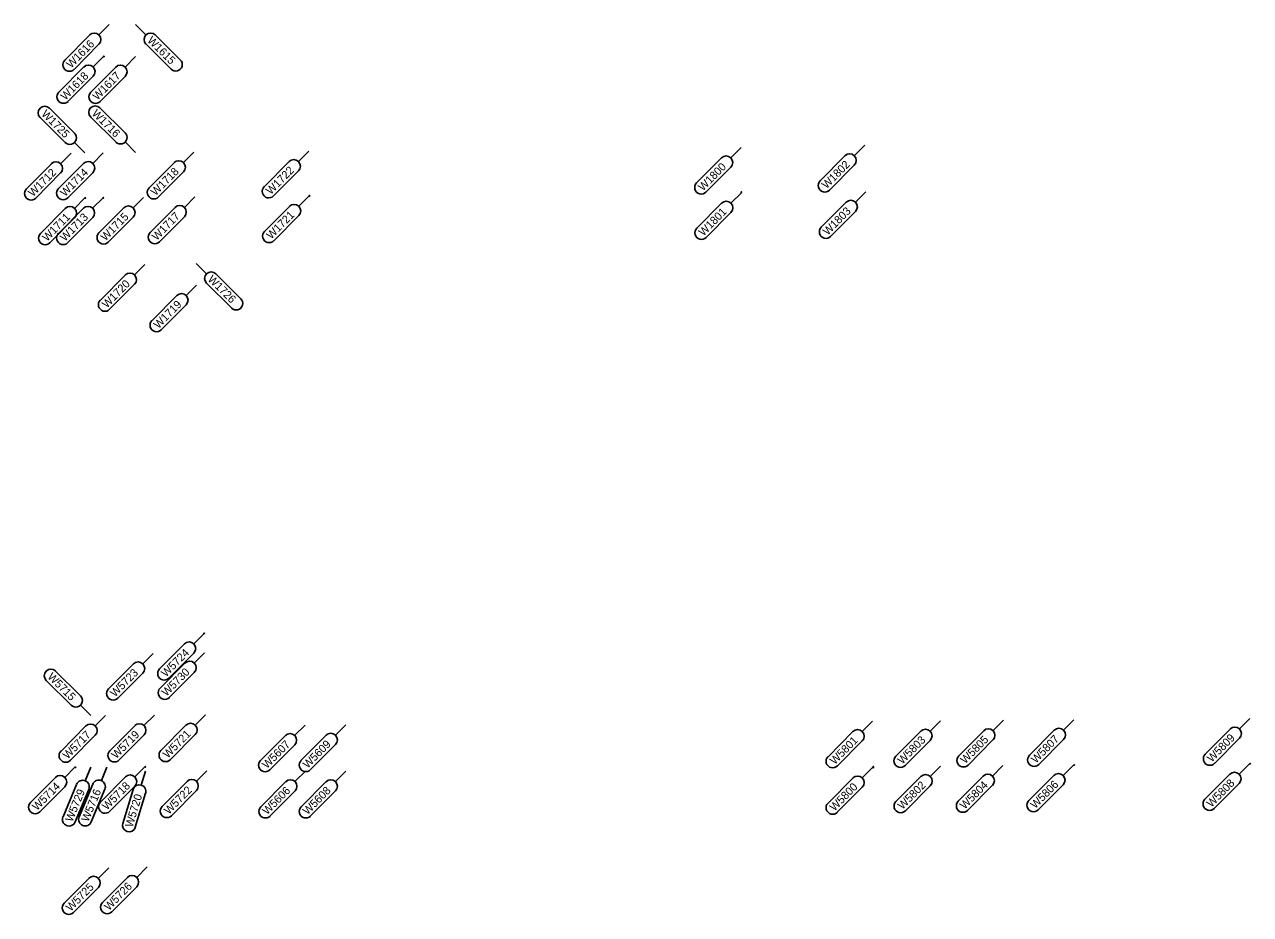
# Model space of a CAD drawing. Extents: x 12479652 to 12487250, y 9842710 to 9846560.
# Drawn here: x 12482796.2 to 12482987.8, y 9842724.8 to 9842863.8 of the extents above; entities that cross this region are included whole.
import ezdxf

# ---------------------------------------------------------------- set-up
doc = ezdxf.new("R2010")
doc.units = 0
doc.layers.add('_CIVIL_CONSTRUCTION', color=7, linetype='Continuous')
doc.layers.add('TextAlignmentLrg', color=7, linetype='Continuous')

msp = doc.modelspace()

# ---------------------------------------------------------------- linework, layer by layer
at = {"layer": '_CIVIL_CONSTRUCTION'}
for p, q in [((12482809.48, 9842863.78), (12482807.86, 9842862.15)), ((12482813.58, 9842863.77), (12482815.21, 9842862.15)), ((12482802.52, 9842858.23), (12482806.41, 9842862.14)), ((12482807.86, 9842860.7), (12482803.98, 9842856.78)), ((12482819.13, 9842856.81), (12482815.22, 9842860.7)), ((12482816.67, 9842862.15), (12482820.58, 9842858.26)), ((12482808.57, 9842858.78), (12482806.95, 9842857.15)), ((12482813.57, 9842858.77), (12482811.95, 9842857.14)), ((12482801.61, 9842853.23), (12482805.5, 9842857.15)), ((12482806.61, 9842853.22), (12482810.5, 9842857.13)), ((12482806.95, 9842855.7), (12482803.06, 9842851.79)), ((12482811.95, 9842855.69), (12482808.06, 9842851.77)), ((12482802.59, 9842845.36), (12482798.68, 9842849.25)), ((12482800.12, 9842850.71), (12482804.04, 9842846.82)), ((12482810.49, 9842845.44), (12482806.58, 9842849.33)), ((12482808.03, 9842850.78), (12482811.94, 9842846.89)), ((12482805.67, 9842843.75), (12482804.04, 9842845.37)), ((12482813.58, 9842843.82), (12482811.94, 9842845.44)), ((12482803.5, 9842843.68), (12482801.88, 9842842.05)), ((12482808.53, 9842843.72), (12482806.9, 9842842.09)), ((12482822.68, 9842843.85), (12482821.06, 9842842.22)), ((12482840.65, 9842844.01), (12482839.03, 9842842.38)), ((12482908.21, 9842844.59), (12482906.58, 9842842.96)), ((12482927.5, 9842844.92), (12482925.87, 9842843.29)), ((12482796.54, 9842838.13), (12482800.43, 9842842.04)), ((12482801.56, 9842838.17), (12482805.45, 9842842.09)), ((12482815.72, 9842838.3), (12482819.61, 9842842.21)), ((12482833.69, 9842838.46), (12482837.58, 9842842.38)), ((12482901.24, 9842839.04), (12482905.13, 9842842.95)), ((12482906.59, 9842841.51), (12482902.7, 9842837.6)), ((12482920.53, 9842839.38), (12482924.42, 9842843.29)), ((12482925.88, 9842841.84), (12482921.99, 9842837.93)), ((12482801.88, 9842840.6), (12482797.99, 9842836.68)), ((12482806.91, 9842840.64), (12482803.02, 9842836.73)), ((12482821.07, 9842840.77), (12482817.18, 9842836.85)), ((12482839.04, 9842840.93), (12482835.15, 9842837.02)), ((12482927.68, 9842837.67), (12482926.06, 9842836.04)), ((12482805.68, 9842836.7), (12482804.06, 9842835.07)), ((12482808.51, 9842836.72), (12482806.88, 9842835.09)), ((12482814.83, 9842836.78), (12482813.21, 9842835.15)), ((12482822.83, 9842836.86), (12482821.21, 9842835.23)), ((12482840.71, 9842837.03), (12482839.08, 9842835.4)), ((12482901.26, 9842831.97), (12482905.15, 9842835.89)), ((12482908.23, 9842837.52), (12482906.6, 9842835.89)), ((12482920.72, 9842832.12), (12482924.61, 9842836.03)), ((12482798.72, 9842831.15), (12482802.61, 9842835.06)), ((12482801.54, 9842831.17), (12482805.43, 9842835.09)), ((12482807.87, 9842831.23), (12482811.76, 9842835.14)), ((12482815.87, 9842831.31), (12482819.76, 9842835.22)), ((12482821.21, 9842833.77), (12482817.32, 9842829.86)), ((12482833.74, 9842831.48), (12482837.63, 9842835.39)), ((12482839.09, 9842833.95), (12482835.2, 9842830.03)), ((12482906.61, 9842834.44), (12482902.72, 9842830.53)), ((12482926.06, 9842834.59), (12482922.17, 9842830.67)), ((12482804.07, 9842833.62), (12482800.18, 9842829.7)), ((12482806.89, 9842833.64), (12482803, 9842829.73)), ((12482813.21, 9842833.7), (12482809.32, 9842829.78)), ((12482815.05, 9842826.31), (12482813.43, 9842824.68)), ((12482823.05, 9842826.48), (12482824.68, 9842824.86)), ((12482808.09, 9842820.76), (12482811.98, 9842824.67)), ((12482826.13, 9842824.86), (12482830.04, 9842820.97)), ((12482813.43, 9842823.23), (12482809.54, 9842819.32)), ((12482823.12, 9842823.1), (12482821.5, 9842821.47)), ((12482828.6, 9842819.52), (12482824.68, 9842823.41)), ((12482816.16, 9842817.55), (12482820.05, 9842821.46)), ((12482821.5, 9842820.01), (12482817.61, 9842816.1)), ((12482824.31, 9842768.71), (12482822.69, 9842767.08)), ((12482817.35, 9842763.16), (12482821.24, 9842767.07)), ((12482816.32, 9842765.58), (12482814.7, 9842763.95)), ((12482822.69, 9842765.62), (12482818.8, 9842761.71)), ((12482824.37, 9842765.7), (12482822.75, 9842764.07)), ((12482809.36, 9842760.03), (12482813.25, 9842763.94)), ((12482817.41, 9842760.15), (12482821.3, 9842764.06)), ((12482803.54, 9842757.49), (12482799.62, 9842761.38)), ((12482801.07, 9842762.83), (12482804.98, 9842758.94)), ((12482814.71, 9842762.5), (12482810.82, 9842758.59)), ((12482822.75, 9842762.62), (12482818.86, 9842758.7)), ((12482806.62, 9842755.87), (12482804.99, 9842757.49)), ((12482808.91, 9842755.89), (12482807.29, 9842754.26)), ((12482816.53, 9842755.94), (12482814.9, 9842754.31)), ((12482824.53, 9842756), (12482822.9, 9842754.36)), ((12482987.67, 9842755.42), (12482986.05, 9842753.79)), ((12482801.95, 9842750.34), (12482805.84, 9842754.25)), ((12482809.56, 9842750.39), (12482813.45, 9842754.3)), ((12482817.56, 9842750.45), (12482821.45, 9842754.36)), ((12482840.06, 9842754.39), (12482838.44, 9842752.76)), ((12482846.43, 9842754.44), (12482844.81, 9842752.8)), ((12482921.77, 9842749.46), (12482925.66, 9842753.37)), ((12482928.73, 9842755.01), (12482927.11, 9842753.38)), ((12482932.37, 9842749.53), (12482936.26, 9842753.45)), ((12482939.33, 9842755.08), (12482937.71, 9842753.45)), ((12482942.2, 9842749.6), (12482946.09, 9842753.51)), ((12482949.16, 9842755.15), (12482947.54, 9842753.52)), ((12482953.23, 9842749.68), (12482957.12, 9842753.59)), ((12482960.19, 9842755.23), (12482958.57, 9842753.59)), ((12482980.71, 9842749.87), (12482984.6, 9842753.78)), ((12482807.29, 9842752.81), (12482803.4, 9842748.89)), ((12482814.91, 9842752.86), (12482811.02, 9842748.95)), ((12482822.91, 9842752.91), (12482819.02, 9842749)), ((12482833.1, 9842748.84), (12482836.99, 9842752.76)), ((12482839.46, 9842748.89), (12482843.35, 9842752.8)), ((12482927.12, 9842751.93), (12482923.23, 9842748.01)), ((12482937.71, 9842752), (12482933.82, 9842748.09)), ((12482947.54, 9842752.07), (12482943.65, 9842748.15)), ((12482958.58, 9842752.14), (12482954.69, 9842748.23)), ((12482986.06, 9842752.33), (12482982.17, 9842748.42)), ((12482838.45, 9842751.31), (12482834.56, 9842747.4)), ((12482844.81, 9842751.35), (12482840.92, 9842747.44)), ((12482804.15, 9842747.85), (12482802.53, 9842746.22)), ((12482806.6, 9842747.82), (12482805.71, 9842745.7)), ((12482809.12, 9842747.84), (12482808.24, 9842745.72)), ((12482815.07, 9842747.93), (12482813.45, 9842746.3)), ((12482928.73, 9842747.77), (12482927.11, 9842746.14)), ((12482939.35, 9842748), (12482937.73, 9842746.37)), ((12482949.09, 9842748.07), (12482947.46, 9842746.44)), ((12482960.12, 9842748.15), (12482958.5, 9842746.52)), ((12482987.62, 9842748.36), (12482986, 9842746.73)), ((12482797.19, 9842742.31), (12482801.08, 9842746.22)), ((12482808.11, 9842742.38), (12482812, 9842746.29)), ((12482815.14, 9842747.22), (12482814.48, 9842745.02)), ((12482824.71, 9842747.24), (12482823.09, 9842745.61)), ((12482840.11, 9842747.19), (12482838.49, 9842745.56)), ((12482846.43, 9842747.19), (12482844.81, 9842745.56)), ((12482921.77, 9842742.22), (12482925.66, 9842746.13)), ((12482932.39, 9842742.45), (12482936.28, 9842746.36)), ((12482942.12, 9842742.52), (12482946.01, 9842746.44)), ((12482953.16, 9842742.6), (12482957.05, 9842746.52)), ((12482980.66, 9842742.81), (12482984.55, 9842746.72)), ((12482802.53, 9842744.77), (12482798.64, 9842740.86)), ((12482802.25, 9842740.05), (12482804.37, 9842745.14)), ((12482806.27, 9842744.36), (12482804.15, 9842739.26)), ((12482804.78, 9842740.07), (12482806.9, 9842745.16)), ((12482808.79, 9842744.37), (12482806.67, 9842739.28)), ((12482813.45, 9842744.85), (12482809.56, 9842740.94)), ((12482811.59, 9842739.05), (12482813.2, 9842744.33)), ((12482817.75, 9842741.69), (12482821.64, 9842745.6)), ((12482823.09, 9842744.16), (12482819.2, 9842740.24)), ((12482833.15, 9842741.64), (12482837.04, 9842745.56)), ((12482838.5, 9842744.11), (12482834.61, 9842740.2)), ((12482839.47, 9842741.64), (12482843.35, 9842745.56)), ((12482844.81, 9842744.11), (12482840.92, 9842740.2)), ((12482927.11, 9842744.69), (12482923.22, 9842740.77)), ((12482937.73, 9842744.92), (12482933.85, 9842741)), ((12482947.47, 9842744.99), (12482943.58, 9842741.08)), ((12482958.5, 9842745.07), (12482954.61, 9842741.16)), ((12482986, 9842745.28), (12482982.11, 9842741.36)), ((12482815.16, 9842743.74), (12482813.55, 9842738.46)), ((12482802.43, 9842726.57), (12482806.32, 9842730.48)), ((12482809.39, 9842732.12), (12482807.77, 9842730.49)), ((12482808.43, 9842726.69), (12482812.32, 9842730.6)), ((12482815.39, 9842732.24), (12482813.77, 9842730.61)), ((12482807.77, 9842729.04), (12482803.88, 9842725.12)), ((12482813.77, 9842729.16), (12482809.88, 9842725.25))]:
    msp.add_line(p, q, dxfattribs=at)
for centre, start, end in [((12482807.14, 9842861.42), 315.1702, 135.1702), ((12482815.94, 9842861.42), 45.1702, 225.1702), ((12482803.25, 9842857.51), 135.1702, 315.1702), ((12482806.22, 9842856.42), 315.1702, 135.1702), ((12482811.22, 9842856.41), 315.1702, 135.1702), ((12482819.85, 9842857.53), 225.1702, 45.1702), ((12482802.33, 9842852.51), 135.1702, 315.1702), ((12482807.33, 9842852.5), 135.1702, 315.1702), ((12482799.4, 9842849.98), 45.1702, 225.1702), ((12482807.3, 9842850.05), 45.1702, 225.1702), ((12482803.31, 9842846.09), 225.1702, 45.1702), ((12482811.22, 9842846.16), 225.1702, 45.1702), ((12482925.15, 9842842.56), 315.1702, 135.1702), ((12482801.15, 9842841.32), 315.1702, 135.1702), ((12482806.18, 9842841.36), 315.1702, 135.1702), ((12482820.34, 9842841.49), 315.1702, 135.1702), ((12482838.31, 9842841.65), 315.1702, 135.1702), ((12482905.86, 9842842.23), 315.1702, 135.1702), ((12482797.26, 9842837.41), 135.1702, 315.1702), ((12482802.29, 9842837.45), 135.1702, 315.1702), ((12482816.45, 9842837.58), 135.1702, 315.1702), ((12482834.42, 9842837.74), 135.1702, 315.1702), ((12482901.97, 9842838.32), 135.1702, 315.1702), ((12482921.26, 9842838.65), 135.1702, 315.1702), ((12482838.36, 9842834.67), 315.1702, 135.1702), ((12482905.88, 9842835.16), 315.1702, 135.1702), ((12482925.34, 9842835.31), 315.1702, 135.1702), ((12482803.34, 9842834.34), 315.1702, 135.1702), ((12482806.16, 9842834.36), 315.1702, 135.1702), ((12482812.48, 9842834.42), 315.1702, 135.1702), ((12482820.48, 9842834.5), 315.1702, 135.1702), ((12482901.99, 9842831.25), 135.1702, 315.1702), ((12482921.45, 9842831.4), 135.1702, 315.1702), ((12482799.45, 9842830.43), 135.1702, 315.1702), ((12482802.27, 9842830.45), 135.1702, 315.1702), ((12482808.6, 9842830.51), 135.1702, 315.1702), ((12482816.6, 9842830.58), 135.1702, 315.1702), ((12482834.47, 9842830.76), 135.1702, 315.1702), ((12482812.7, 9842823.95), 315.1702, 135.1702), ((12482825.41, 9842824.13), 45.1702, 225.1702), ((12482808.81, 9842820.04), 135.1702, 315.1702), ((12482820.77, 9842820.74), 315.1702, 135.1702), ((12482829.32, 9842820.24), 225.1702, 45.1702), ((12482816.88, 9842816.83), 135.1702, 315.1702), ((12482821.96, 9842766.35), 315.1702, 135.1702), ((12482800.35, 9842762.11), 45.1702, 225.1702), ((12482813.98, 9842763.22), 315.1702, 135.1702), ((12482818.07, 9842762.43), 135.1702, 315.1702), ((12482822.03, 9842763.34), 315.1702, 135.1702), ((12482810.09, 9842759.31), 135.1702, 315.1702), ((12482818.14, 9842759.43), 135.1702, 315.1702), ((12482804.26, 9842758.22), 225.1702, 45.1702), ((12482806.56, 9842753.53), 315.1702, 135.1702), ((12482814.18, 9842753.58), 315.1702, 135.1702), ((12482822.18, 9842753.64), 315.1702, 135.1702), ((12482926.39, 9842752.65), 315.1702, 135.1702), ((12482936.99, 9842752.72), 315.1702, 135.1702), ((12482946.82, 9842752.79), 315.1702, 135.1702), ((12482957.85, 9842752.87), 315.1702, 135.1702), ((12482985.33, 9842753.06), 315.1702, 135.1702), ((12482837.72, 9842752.03), 315.1702, 135.1702), ((12482844.08, 9842752.08), 315.1702, 135.1702), ((12482802.67, 9842749.62), 135.1702, 315.1702), ((12482810.29, 9842749.67), 135.1702, 315.1702), ((12482818.29, 9842749.72), 135.1702, 315.1702), ((12482933.1, 9842748.81), 135.1702, 315.1702), ((12482942.93, 9842748.88), 135.1702, 315.1702), ((12482953.96, 9842748.95), 135.1702, 315.1702), ((12482981.44, 9842749.15), 135.1702, 315.1702), ((12482833.83, 9842748.12), 135.1702, 315.1702), ((12482840.19, 9842748.16), 135.1702, 315.1702), ((12482922.5, 9842748.74), 135.1702, 315.1702), ((12482801.8, 9842745.5), 315.1702, 135.1702), ((12482805.32, 9842744.75), 337.4033, 157.4033), ((12482807.84, 9842744.77), 337.4033, 157.4033), ((12482812.73, 9842745.57), 315.1702, 135.1702), ((12482822.36, 9842744.88), 315.1702, 135.1702), ((12482837.77, 9842744.83), 315.1702, 135.1702), ((12482844.08, 9842744.83), 315.1702, 135.1702), ((12482926.39, 9842745.41), 315.1702, 135.1702), ((12482937.01, 9842745.64), 315.1702, 135.1702), ((12482946.74, 9842745.71), 315.1702, 135.1702), ((12482957.77, 9842745.79), 315.1702, 135.1702), ((12482985.28, 9842746), 315.1702, 135.1702), ((12482814.18, 9842744.04), 343.0968, 163.0968), ((12482797.91, 9842741.58), 135.1702, 315.1702), ((12482808.84, 9842741.66), 135.1702, 315.1702), ((12482922.5, 9842741.5), 135.1702, 315.1702), ((12482933.12, 9842741.73), 135.1702, 315.1702), ((12482942.85, 9842741.8), 135.1702, 315.1702), ((12482953.88, 9842741.88), 135.1702, 315.1702), ((12482981.39, 9842742.09), 135.1702, 315.1702), ((12482803.2, 9842739.66), 157.4033, 337.4033), ((12482805.72, 9842739.67), 157.4033, 337.4033), ((12482818.48, 9842740.97), 135.1702, 315.1702), ((12482833.88, 9842740.92), 135.1702, 315.1702), ((12482840.19, 9842740.92), 135.1702, 315.1702), ((12482812.57, 9842738.76), 163.0968, 343.0968), ((12482807.04, 9842729.76), 315.1702, 135.1702), ((12482813.04, 9842729.88), 315.1702, 135.1702), ((12482803.15, 9842725.85), 135.1702, 315.1702), ((12482809.15, 9842725.97), 135.1702, 315.1702)]:
    msp.add_arc(centre, 1.03, start, end, dxfattribs=at)
at = {"layer": 'TextAlignmentLrg'}
for centre in [(12482808.62, 9842858.78), (12482908.23, 9842837.62), (12482805.73, 9842836.7), (12482808.56, 9842836.72), (12482840.76, 9842837.03), (12482824.31, 9842768.71), (12482804.2, 9842747.8), (12482815.12, 9842747.88), (12482928.83, 9842747.77), (12482928.86, 9842747.9), (12482960.22, 9842748.15), (12482987.72, 9842748.36)]:
    msp.add_circle(centre, 0.05, dxfattribs=at)

# ---------------------------------------------------------------- texts
at = {"layer": '_CIVIL_CONSTRUCTION'}
for s, rotation, p in [('W1616', 45.1702, (12482803.52, 9842856.88)), ('W1615', 315.1702, (12482815.32, 9842861.18)), ('W1618', 45.1702, (12482802.61, 9842851.88)), ('W1617', 45.1702, (12482807.62, 9842851.88)), ('W1725', 315.1702, (12482798.78, 9842849.7)), ('W1716', 315.1702, (12482806.67, 9842849.78)), ('W1722', 45.1702, (12482834.71, 9842837.13)), ('W1800', 45.1702, (12482902.24, 9842837.69)), ('W1802', 45.1702, (12482921.55, 9842838.04)), ('W1712', 45.1702, (12482797.56, 9842836.8)), ('W1714', 45.1702, (12482802.56, 9842836.82)), ('W1718', 45.1702, (12482816.72, 9842836.95)), ('W1711', 45.1702, (12482799.76, 9842829.83)), ('W1713', 45.1702, (12482802.55, 9842829.83)), ('W1715', 45.1702, (12482808.88, 9842829.89)), ('W1717', 45.1702, (12482816.88, 9842829.97)), ('W1721', 45.1702, (12482834.78, 9842830.17)), ('W1801', 45.1702, (12482902.3, 9842830.66)), ('W1803', 45.1702, (12482921.72, 9842830.78)), ('W1726', 315.1702, (12482824.77, 9842823.9)), ('W1720', 45.1702, (12482809.09, 9842819.41)), ('W1719', 45.1702, (12482817.16, 9842816.2)), ('W5724', 45.1702, (12482818.34, 9842761.8)), ('W5723', 45.1702, (12482810.37, 9842758.69)), ('W5730', 45.1702, (12482818.41, 9842758.8)), ('W5715', 315.1702, (12482799.73, 9842761.82)), ('W5717', 45.1702, (12482802.96, 9842749)), ('W5719', 45.1702, (12482810.56, 9842749.04)), ('W5721', 45.1702, (12482818.6, 9842749.13)), ('W5607', 45.1702, (12482834.11, 9842747.5)), ('W5609', 45.1702, (12482840.47, 9842747.54)), ('W5801', 45.1702, (12482922.81, 9842748.14)), ('W5803', 45.1702, (12482933.38, 9842748.19)), ('W5805', 45.1702, (12482943.21, 9842748.26)), ('W5807', 45.1702, (12482954.24, 9842748.34)), ('W5809', 45.1702, (12482981.71, 9842748.52)), ('W5806', 45.1702, (12482954.15, 9842741.25)), ('W5808', 45.1702, (12482981.66, 9842741.46)), ('W5714', 45.1702, (12482798.18, 9842740.95)), ('W5729', 67.4033, (12482803.69, 9842739.18)), ('W5716', 67.4033, (12482806.21, 9842739.19)), ('W5718', 45.1702, (12482809.11, 9842741.03)), ('W5722', 45.1702, (12482818.77, 9842740.36)), ('W5606', 45.1702, (12482834.15, 9842740.29)), ('W5608', 45.1702, (12482840.46, 9842740.29)), ('W5800', 45.1702, (12482922.77, 9842740.87)), ('W5802', 45.1702, (12482933.41, 9842741.12)), ('W5804', 45.1702, (12482943.12, 9842741.16)), ('W5720', 73.0968, (12482813.11, 9842738.33)), ('W5725', 45.1702, (12482803.44, 9842725.23)), ('W5726', 45.1702, (12482809.42, 9842725.34))]:
    msp.add_text(s, height=1.25, rotation=rotation, dxfattribs=at).set_placement(p)

doc.saveas('drawing.dxf')
